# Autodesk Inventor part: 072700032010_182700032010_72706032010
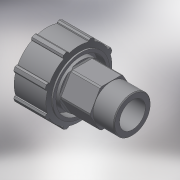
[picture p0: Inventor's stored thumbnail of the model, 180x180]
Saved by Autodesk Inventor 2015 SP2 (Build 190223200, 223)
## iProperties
Created: 2017-04
Part Number: 072700032010_182700032010_72706032010
Material: Generic
Description: PLASSON BRASS THREADED ADAPTOR 32-1"
Document SubType Name: Modeling
Designer: KIM
Density: 1 g/cm^3
Appearance: Default
Author: KIM
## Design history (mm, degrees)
derived "07270.ipt"
feature "Solid1::07270.ipt"
tag "TaggingFeature1"
body "Solid1"
other parameters: "d1" = 33.249, "d2" = 77, "d3" = 19, "d7" = 64, "d8" = 51.2, "d9" = 32, "d12" = 23.2743, "d13" = 26.5992, "d15" = 48, "d17" = 30.8, "d18" = 19, "d19" = 22.8, "d40" = 34, "d41" = 39.1, "d42" = 135 deg, "d43" = 100 deg, "d44" = 28.336, "d45" = 45.6, "d46" = 59.52, "d47" = 35 deg, "d48" = 17.5 deg, "d50" = 0, "d52" = 360 deg, "d54" = 1.28, "d57" = 1.28, "d61" = 0, "d62" = 0.66498, "d65" = 0.99747, "d_" = 32, "R_" = 33.249, "E_" = 64, "H_" = 77, "l_2" = 19, "Wrench" = 34
